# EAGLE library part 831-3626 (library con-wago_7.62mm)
Serie 831, Stiftleiste (für Leiterplatten) mit abgewinkelten Einlötstiften / Series 831, Male header (for PCBs) with angled solder pins Polzahl / Pole No.: 6 Bemessungsspannung / Rated Voltage: 630 V Nennstrom / Nominal Current: 41 A Lötstiftlänge: / Solder Pin Length: 4 mm Farbe / Color: lichtgrau / light gray Stand: 01.01.2012. Die jeweils aktuellen Daten zu diesem Artikel finden Sie in unserem Produktkatalog, den Sie unter www.wago.com einsehen können. As of: 01/01/2012. Please find the newest data for this article in our product catalogue, which can be viewed under www.wago.com.
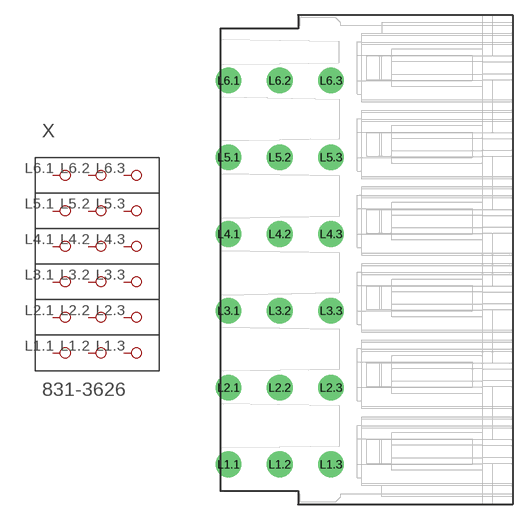
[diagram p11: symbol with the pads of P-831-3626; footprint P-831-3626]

Designator prefix X

## 831-3626  [P-831-3626]
L1.1  P1.1
L1.2  P1.2
L1.3  P1.3
L2.1  P2.1
L2.2  P2.2
L2.3  P2.3
L3.1  P3.1
L3.2  P3.2
L3.3  P3.3
L4.1  P4.1
L4.2  P4.2
L4.3  P4.3
L5.1  P5.1
L5.2  P5.2
L5.3  P5.3
L6.1  P6.1
L6.2  P6.2
L6.3  P6.3

## Footprint P-831-3626 (pad centres in mm)
drill 1.7 round: L1.1 -13.7,-20.32; L1.2 -8.62,-20.32; L1.3 -3.54,-20.32; L2.1 -13.7,-12.7; L2.2 -8.62,-12.7; L2.3 -3.54,-12.7; L3.1 -13.7,-5.06; L3.2 -8.62,-5.06; L3.3 -3.54,-5.06; L4.1 -13.7,2.56; L4.2 -8.62,2.56; L4.3 -3.54,2.56; L5.1 -13.7,10.18; L5.2 -8.62,10.18; L5.3 -3.54,10.18; L6.1 -13.7,17.8; L6.2 -8.62,17.8; L6.3 -3.54,17.8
